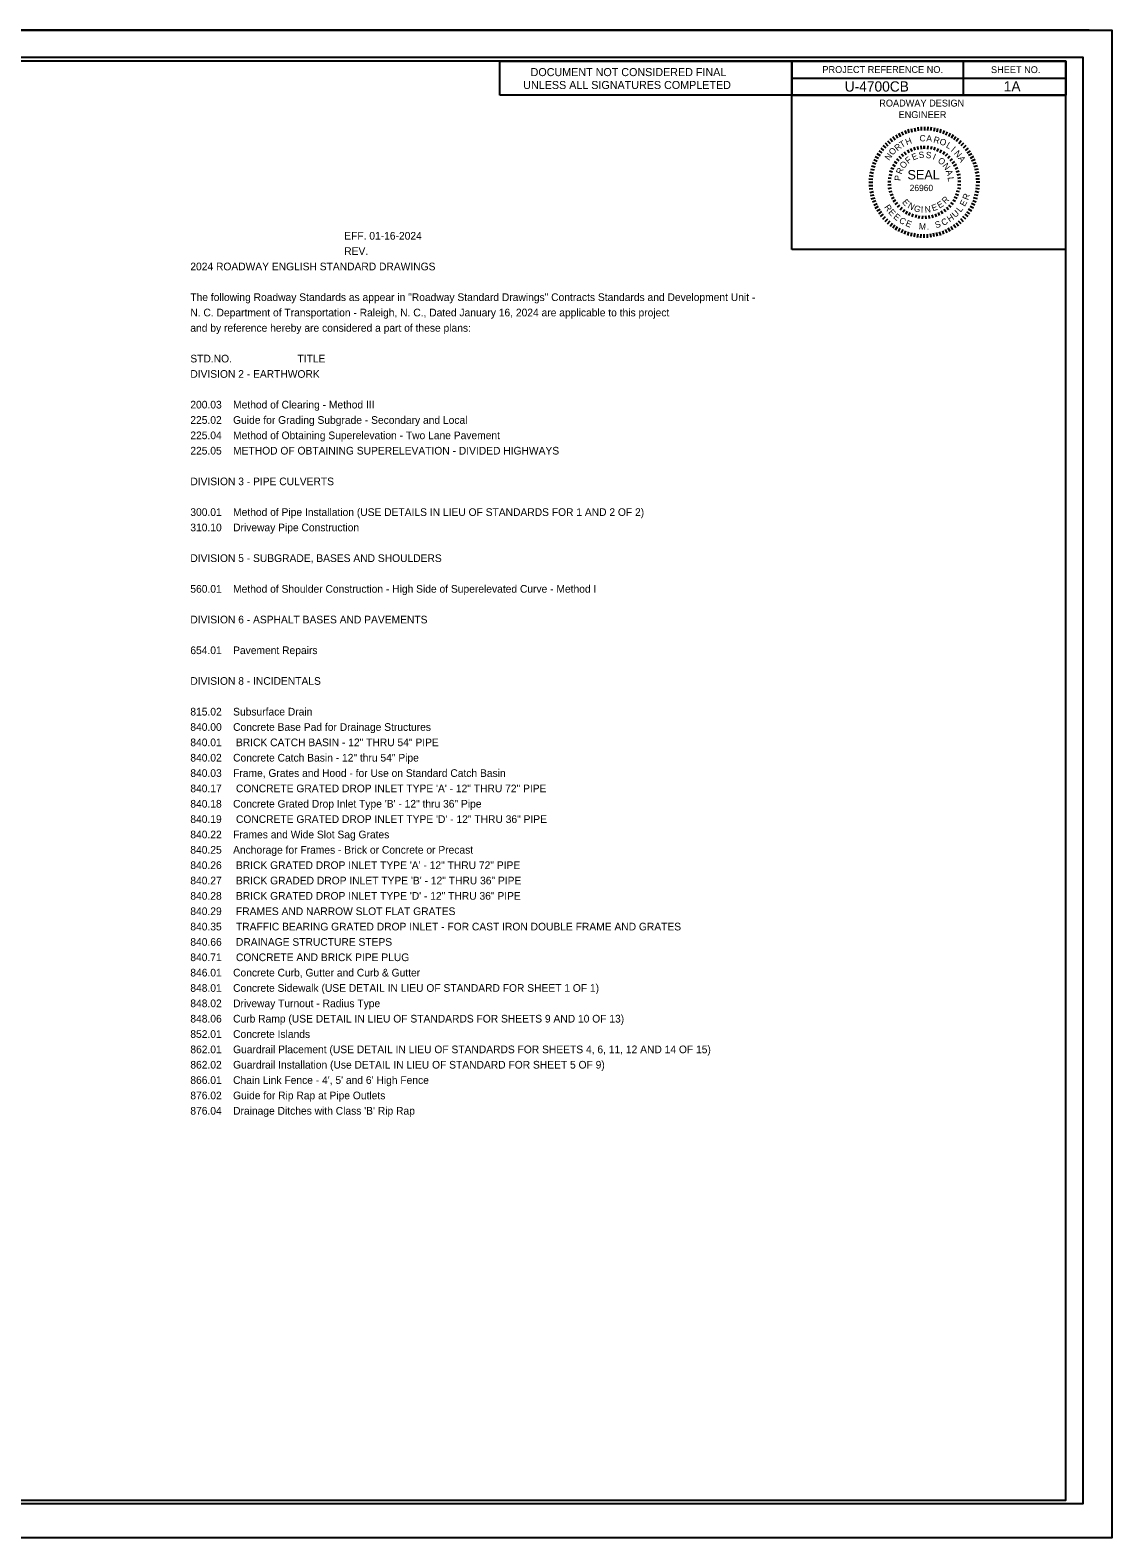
# Model space of a CAD drawing. Extents: x 573687 to 575387, y -53365 to -52265.
# Drawn here: x 574597 to 575387, y -53365 to -52265 of the extents above; entities that cross this region are included whole.
import ezdxf

# ---------------------------------------------------------------- set-up
doc = ezdxf.new("R2010")
doc.units = 0
for name, color, linetype in [('Default', 7, 'Continuous'), ('Sheet Cutting Line CELL', 7, 'Continuous'), ('Sheet Data Field CELL', 7, 'Continuous'), ('Sheet Data Text CELL', 7, 'Continuous'), ('Sheet Plan CELL', 7, 'Continuous'), ('Sheet Plot Border Inside CELL', 7, 'Continuous'), ('Sheet Plot Border Outside CELL', 7, 'Continuous'), ('Sheet Sticker Exception Certification CELL', 7, 'Continuous')]:
    doc.layers.add(name, color=color, linetype=linetype)

msp = doc.modelspace()

# ---------------------------------------------------------------- linework, layer by layer
at = {"layer": 'Default'}
for p, q in [((575237.8, -52337.2), (575238.6, -52339.9)), ((575240.2, -52336.6), (575240.8, -52339.2)), ((575242.6, -52336.1), (575243, -52338.8)), ((575245, -52335.7), (575245.3, -52338.4)), ((575247.4, -52335.5), (575247.6, -52338.2)), ((575249.9, -52335.4), (575249.9, -52338.2)), ((575252.3, -52335.5), (575252.1, -52338.2)), ((575254.7, -52335.7), (575254.4, -52338.4)), ((575257.2, -52336.1), (575256.7, -52338.8)), ((575259.5, -52336.6), (575258.9, -52339.3)), ((575261.9, -52337.2), (575261.1, -52339.9)), ((575221.2, -52347.2), (575223.2, -52349.2)), ((575223, -52345.6), (575224.8, -52347.6)), ((575224.9, -52344), (575226.6, -52346.2)), ((575226.8, -52342.5), (575228.4, -52344.8)), ((575228.9, -52341.2), (575230.3, -52343.6)), ((575231, -52340), (575232.3, -52342.5)), ((575233.2, -52339), (575234.4, -52341.5)), ((575235.5, -52338), (575236.5, -52340.6)), ((575264.2, -52338), (575263.2, -52340.6)), ((575266.5, -52339), (575265.3, -52341.5)), ((575268.7, -52340), (575267.4, -52342.5)), ((575270.8, -52341.3), (575269.4, -52343.6)), ((575272.9, -52342.6), (575271.3, -52344.9)), ((575274.8, -52344), (575273.1, -52346.2)), ((575276.7, -52345.6), (575274.9, -52347.7)), ((575278.5, -52347.3), (575276.5, -52349.2)), ((575212.9, -52359.2), (575215.4, -52360.4)), ((575214, -52357), (575216.4, -52358.3)), ((575215.2, -52354.9), (575217.5, -52356.3)), ((575216.5, -52352.9), (575218.8, -52354.4)), ((575218, -52350.9), (575220.1, -52352.6)), ((575219.5, -52349), (575221.6, -52350.8)), ((575229.4, -52358.7), (575231.2, -52360.1)), ((575231.2, -52356.8), (575232.8, -52358.4)), ((575233.1, -52355.1), (575234.6, -52356.9)), ((575235.2, -52353.6), (575236.5, -52355.5)), ((575237.4, -52352.2), (575238.5, -52354.3)), ((575239.8, -52351.2), (575240.6, -52353.3)), ((575242.2, -52350.3), (575242.9, -52352.5)), ((575244.7, -52349.7), (575245.1, -52352)), ((575247.3, -52349.3), (575247.5, -52351.6)), ((575249.8, -52349.2), (575249.8, -52351.5)), ((575249.8, -52351.5), (575249.8, -52349.2)), ((575252.4, -52349.3), (575252.2, -52351.6)), ((575255, -52349.7), (575254.5, -52352)), ((575257.5, -52350.3), (575256.8, -52352.5)), ((575259.9, -52351.2), (575259, -52353.3)), ((575262.2, -52352.3), (575261.2, -52354.3)), ((575264.5, -52353.6), (575263.2, -52355.5)), ((575266.6, -52355.1), (575265.1, -52356.9)), ((575268.5, -52356.8), (575266.9, -52358.5)), ((575270.2, -52358.7), (575268.5, -52360.2)), ((575280.2, -52349.1), (575278.1, -52350.9)), ((575281.7, -52350.9), (575279.5, -52352.6)), ((575283.2, -52352.9), (575280.9, -52354.5)), ((575284.5, -52355), (575282.1, -52356.4)), ((575285.7, -52357.1), (575283.2, -52358.4)), ((575286.8, -52359.3), (575284.2, -52360.4)), ((575209.6, -52371), (575212.4, -52371.3)), ((575210, -52368.6), (575212.7, -52369.1)), ((575210.5, -52366.2), (575213.2, -52366.8)), ((575211.2, -52363.8), (575213.8, -52364.6)), ((575212, -52361.5), (575214.5, -52362.5)), ((575223.8, -52370.1), (575226, -52370.6)), ((575224.4, -52367.6), (575226.6, -52368.3)), ((575225.4, -52365.2), (575227.5, -52366.1)), ((575226.5, -52362.9), (575228.5, -52364)), ((575227.9, -52360.7), (575229.8, -52362)), ((575271.8, -52360.8), (575269.9, -52362.1)), ((575273.2, -52362.9), (575271.1, -52364.1)), ((575274.3, -52365.3), (575272.2, -52366.2)), ((575275.2, -52367.7), (575273, -52368.4)), ((575275.9, -52370.2), (575273.6, -52370.7)), ((575287.7, -52361.6), (575285.1, -52362.5)), ((575288.5, -52363.9), (575285.9, -52364.7)), ((575289.1, -52366.2), (575286.5, -52366.9)), ((575289.7, -52368.6), (575286.9, -52369.1)), ((575209.3, -52375.9), (575212.1, -52375.9)), ((575209.4, -52373.4), (575212.1, -52373.6)), ((575209.4, -52378.3), (575212.1, -52378.1)), ((575209.6, -52380.7), (575212.3, -52380.4)), ((575223.1, -52375.2), (575225.4, -52375.3)), ((575223.2, -52377.8), (575225.5, -52377.6)), ((575223.3, -52372.7), (575225.6, -52372.9)), ((575223.5, -52380.4), (575225.8, -52380)), ((575273.9, -52379.9), (575276.1, -52380.3)), ((575276.3, -52372.7), (575274, -52373)), ((575276.4, -52377.9), (575274.1, -52377.7)), ((575276.5, -52375.3), (575274.2, -52375.3)), ((575290, -52371.1), (575287.3, -52371.4)), ((575290, -52380.8), (575287.3, -52380.5)), ((575290.2, -52373.5), (575287.5, -52373.6)), ((575290.2, -52378.4), (575287.5, -52378.2)), ((575290.3, -52375.9), (575287.6, -52375.9)), ((575210, -52383.2), (575212.7, -52382.7)), ((575210.5, -52385.5), (575213.2, -52384.9)), ((575211.1, -52387.9), (575213.8, -52387.1)), ((575211.9, -52390.2), (575214.5, -52389.2)), ((575212.9, -52392.5), (575215.4, -52391.4)), ((575224.1, -52382.9), (575226.3, -52382.3)), ((575224.8, -52385.3), (575227, -52384.5)), ((575225.9, -52387.7), (575227.9, -52386.7)), ((575227.1, -52390), (575229.1, -52388.7)), ((575228.6, -52392.1), (575230.4, -52390.7)), ((575230.3, -52394.1), (575231.9, -52392.5)), ((575269.3, -52394.1), (575267.7, -52392.5)), ((575271, -52392.1), (575269.2, -52390.7)), ((575272.5, -52390), (575270.5, -52388.8)), ((575273.7, -52387.7), (575271.7, -52386.7)), ((575274.8, -52385.4), (575272.6, -52384.6)), ((575275.6, -52382.9), (575273.3, -52382.3)), ((575286.7, -52392.5), (575284.2, -52391.4)), ((575287.7, -52390.3), (575285.1, -52389.3)), ((575288.5, -52388), (575285.8, -52387.2)), ((575289.1, -52385.6), (575286.5, -52385)), ((575289.6, -52383.2), (575286.9, -52382.7)), ((575213.9, -52394.7), (575216.4, -52393.4)), ((575215.1, -52396.8), (575217.5, -52395.4)), ((575216.5, -52398.9), (575218.7, -52397.3)), ((575217.9, -52400.8), (575220.1, -52399.1)), ((575219.5, -52402.7), (575221.5, -52400.9)), ((575221.2, -52404.5), (575223.1, -52402.6)), ((575232.1, -52395.9), (575233.6, -52394.1)), ((575234.1, -52397.5), (575235.5, -52395.6)), ((575236.3, -52398.9), (575237.4, -52396.9)), ((575238.5, -52400.1), (575239.5, -52398)), ((575240.9, -52401.1), (575241.7, -52398.9)), ((575243.9, -52399.6), (575243.4, -52401.8)), ((575245.9, -52402.3), (575246.3, -52400)), ((575248.5, -52402.6), (575248.6, -52400.3)), ((575251.1, -52402.6), (575251, -52400.3)), ((575253.6, -52402.3), (575253.3, -52400)), ((575256.2, -52401.8), (575255.6, -52399.6)), ((575258.6, -52401.1), (575257.9, -52398.9)), ((575261, -52400.1), (575260.1, -52398)), ((575263.3, -52398.9), (575262.2, -52396.9)), ((575265.5, -52397.5), (575264.1, -52395.6)), ((575267.5, -52395.9), (575266, -52394.2)), ((575278.4, -52404.6), (575276.5, -52402.6)), ((575280.1, -52402.8), (575278, -52400.9)), ((575281.7, -52400.9), (575279.5, -52399.2)), ((575283.1, -52398.9), (575280.9, -52397.4)), ((575284.5, -52396.9), (575282.1, -52395.4)), ((575285.7, -52394.7), (575283.2, -52393.5)), ((575222.9, -52406.2), (575224.8, -52404.1)), ((575224.8, -52407.8), (575226.5, -52405.6)), ((575226.8, -52409.2), (575228.3, -52406.9)), ((575228.8, -52410.5), (575230.3, -52408.2)), ((575231, -52411.7), (575232.2, -52409.3)), ((575233.2, -52412.8), (575234.3, -52410.3)), ((575235.4, -52413.8), (575236.4, -52411.2)), ((575237.7, -52414.6), (575238.6, -52411.9)), ((575240.1, -52415.2), (575240.7, -52412.5)), ((575242.5, -52415.7), (575243, -52413)), ((575244.9, -52416.1), (575245.2, -52413.4)), ((575247.3, -52416.3), (575247.5, -52413.6)), ((575249.8, -52416.4), (575249.8, -52413.6)), ((575252.2, -52416.3), (575252.1, -52413.6)), ((575254.7, -52416.1), (575254.3, -52413.4)), ((575257.1, -52415.7), (575256.6, -52413)), ((575259.5, -52415.2), (575258.8, -52412.5)), ((575261.8, -52414.6), (575261, -52411.9)), ((575264.1, -52413.8), (575263.2, -52411.2)), ((575266.4, -52412.8), (575265.3, -52410.3)), ((575268.6, -52411.8), (575267.3, -52409.3)), ((575270.7, -52410.6), (575269.3, -52408.2)), ((575272.8, -52409.2), (575271.2, -52407)), ((575274.8, -52407.8), (575273.1, -52405.6)), ((575276.6, -52406.2), (575274.8, -52404.2))]:
    msp.add_line(p, q, dxfattribs=at)
at = {"layer": 'Sheet Cutting Line CELL'}
msp.add_line((575370.2, -52264.9), (573686.7, -52264.9), dxfattribs=at)
at = {"layer": 'Sheet Plan CELL'}
for p, q in [((575278.2, -52287.4), (575278.2, -52312.4)), ((575153.2, -52299.9), (575353.2, -52299.9)), ((575153.2, -52312.4), (575353.2, -52312.4)), ((575153.2, -52312.4), (575353.2, -52312.4)), ((575153.2, -52424.9), (575153.2, -52312.4)), ((575221.8, -52312.4), (575353.2, -52312.4)), ((575353.2, -52424.9), (575153.2, -52424.9))]:
    msp.add_line(p, q, dxfattribs=at)
for points in [[(575353.2, -52287.4), (573853.2, -52287.4), (573853.2, -53337.4), (575353.2, -53337.4)], [(575153.2, -52287.4), (575353.2, -52287.4), (575353.2, -52312.4), (575153.2, -52312.4)]]:
    msp.add_lwpolyline(points, close=True, dxfattribs=at)
at = {"layer": 'Sheet Plot Border Inside CELL'}
msp.add_lwpolyline([(573699.7, -53339.9), (575365.7, -53339.9), (575365.7, -52284.9), (573699.7, -52284.9)], close=True, dxfattribs=at)
at = {"layer": 'Sheet Plot Border Outside CELL'}
msp.add_lwpolyline([(573686.7, -52264.9), (575386.7, -52264.9), (575386.7, -53364.9), (573686.7, -53364.9)], close=True, dxfattribs=at)
at = {"layer": 'Sheet Sticker Exception Certification CELL'}
for p, q in [((574939.9, -52312.4), (574939.9, -52287.4)), ((574939.9, -52287.4), (575153.2, -52287.4)), ((575153.2, -52287.4), (575153.2, -52312.4)), ((575153.2, -52312.4), (574939.9, -52312.4))]:
    msp.add_line(p, q, dxfattribs=at)

# ---------------------------------------------------------------- texts
at = {"layer": 'Default'}
for s, height, rotation, p in [('R', 4.6, 38.6075, (575230.2, -52353.4)), ('T', 4.6, 30.4466, (575233.3, -52350.9)), ('H', 4.6, 21.0146, (575237, -52348.9)), ('C', 4.6, 357.3039, (575246.2, -52345.9)), ('A', 4.6, 357.3039, (575251.2, -52346)), ('R', 4.6, 345.2946, (575256.1, -52346.7)), ('O', 4.6, 342.2378, (575260.5, -52348)), ('L', 4.6, 329.1015, (575265.2, -52350.1)), ('N', 4.6, 53.6237, (575224.2, -52360.4)), ('O', 4.6, 51.6643, (575226.9, -52356.5)), ('F', 4.6, 38.1876, (575238, -52362.6)), ('E', 4.6, 22.8914, (575241.7, -52360)), ('S', 4.6, 7.5951, (575246, -52358.4)), ('S', 4.6, 352.2989, (575250.6, -52358)), ('I', 4.6, 337.0026, (575255.5, -52359)), ('O', 4.6, 321.7064, (575259.2, -52360.8)), ('I', 4.6, 319.5261, (575268.9, -52352.8)), ('N', 4.6, 310.2316, (575271.2, -52354.9)), ('A', 4.6, 300.4641, (575274.2, -52358.3)), ('P', 4.6, 84.0763, (575232.5, -52375)), ('R', 4.6, 68.7801, (575233.2, -52370.4)), ('O', 4.6, 53.4838, (575235, -52366.3)), ('SEAL', 6.9, 359.947, (575237.5, -52373.8)), ('N', 4.6, 306.4101, (575262.8, -52363.9)), ('A', 4.6, 291.1139, (575265.3, -52367.7)), ('26960', 4.6, 359.947, (575239.1, -52382.3)), ('L', 4.6, 275.8176, (575266.8, -52372.2)), ('R', 4.6, 303.882, (575220.3, -52394)), ('E', 4.6, 310.0171, (575233.3, -52390.5)), ('N', 4.6, 330.8721, (575237.2, -52394.3)), ('G', 4.6, 339.6384, (575241.7, -52396.5)), ('E', 4.6, 20.7549, (575256.1, -52397.1)), ('E', 4.6, 30.7408, (575260.8, -52395.1)), ('R', 4.6, 44.5119, (575265.2, -52391.9)), ('E', 4.6, 60.9466, (575279.3, -52393.9)), ('R', 4.6, 69.6194, (575281.7, -52389.2)), ('E', 4.6, 311.9538, (575223.2, -52398)), ('E', 4.6, 320.5966, (575226.8, -52401.7)), ('C', 4.6, 329.2691, (575230.9, -52404.9)), ('E', 4.6, 338.2416, (575235.7, -52407.5)), ('I', 4.6, 357.7332, (575247.2, -52398)), ('N', 4.6, 5.3628, (575250.3, -52398.1)), ('C', 4.6, 25.5662, (575263.5, -52407.7)), ('H', 4.6, 34.3888, (575268.3, -52405.1)), ('U', 4.6, 43.2714, (575272.4, -52402)), ('L', 4.6, 52.154, (575276.3, -52398.1)), ('M', 4.6, 356.0369, (575245.7, -52410.2)), ('.', 4.6, 3.7793, (575251.7, -52410.4)), ('S', 4.6, 16.5636, (575258.3, -52409.4))]:
    msp.add_text(s, height=height, rotation=rotation, dxfattribs=at).set_placement(p)
at = {"layer": 'Sheet Data Field CELL'}
for s, p in [('U-4700CB', (575191.7, -52309.7)), ('1A ', (575307.8, -52309.6))]:
    msp.add_text(s, height=7.5, dxfattribs=at).set_placement(p)
at = {"layer": 'Sheet Data Text CELL'}
for s, p in [('                                                      EFF. 01-16-2024', (574714, -52417.7)), ('                                                      REV. ', (574714, -52428.9)), ('2024 ROADWAY ENGLISH STANDARD DRAWINGS', (574714, -52440.1)), ('The following Roadway Standards as appear in "Roadway Standard Drawings" Contracts Standards and Development Unit -', (574714, -52462.5)), ('N. C. Department of Transportation - Raleigh, N. C., Dated January 16, 2024 are applicable to this project', (574714, -52473.7)), ('and by reference hereby are considered a part of these plans:', (574714, -52484.9)), ('STD.NO.                       TITLE', (574714, -52507.3)), ('DIVISION 2 - EARTHWORK', (574714, -52518.5)), ('200.03    Method of Clearing - Method III', (574714, -52540.9)), ('225.02    Guide for Grading Subgrade - Secondary and Local', (574714, -52552.1)), ('225.04    Method of Obtaining Superelevation - Two Lane Pavement', (574714, -52563.3)), ('225.05    METHOD OF OBTAINING SUPERELEVATION - DIVIDED HIGHWAYS', (574714, -52574.5)), ('DIVISION 3 - PIPE CULVERTS', (574714, -52596.9)), ('300.01    Method of Pipe Installation (USE DETAILS IN LIEU OF STANDARDS FOR 1 AND 2 OF 2)', (574714, -52619.3)), ('310.10    Driveway Pipe Construction', (574714, -52630.5)), ('DIVISION 5 - SUBGRADE, BASES AND SHOULDERS', (574714, -52652.9)), ('560.01    Method of Shoulder Construction - High Side of Superelevated Curve - Method I', (574714, -52675.3)), ('DIVISION 6 - ASPHALT BASES AND PAVEMENTS', (574714, -52697.7)), ('654.01    Pavement Repairs', (574714, -52720.1)), ('DIVISION 8 - INCIDENTALS', (574714, -52742.5)), ('815.02    Subsurface Drain', (574714, -52764.9)), ('840.00    Concrete Base Pad for Drainage Structures', (574714, -52776.1)), ('840.01     BRICK CATCH BASIN - 12" THRU 54" PIPE', (574714, -52787.3)), ('840.02    Concrete Catch Basin - 12" thru 54" Pipe', (574714, -52798.5)), ('840.03    Frame, Grates and Hood - for Use on Standard Catch Basin', (574714, -52809.7)), ('840.17     CONCRETE GRATED DROP INLET TYPE \'A\' - 12" THRU 72" PIPE', (574714, -52820.9)), ('840.18    Concrete Grated Drop Inlet Type \'B\' - 12" thru 36" Pipe', (574714, -52832.1)), ('840.19     CONCRETE GRATED DROP INLET TYPE \'D\' - 12" THRU 36" PIPE', (574714, -52843.3)), ('840.22    Frames and Wide Slot Sag Grates', (574714, -52854.5)), ('840.25    Anchorage for Frames - Brick or Concrete or Precast', (574714, -52865.7)), ('840.26     BRICK GRATED DROP INLET TYPE \'A\' - 12" THRU 72" PIPE', (574714, -52876.9)), ('840.27     BRICK GRADED DROP INLET TYPE \'B\' - 12" THRU 36" PIPE', (574714, -52888.1)), ('840.28     BRICK GRATED DROP INLET TYPE \'D\' - 12" THRU 36" PIPE', (574714, -52899.3)), ('840.29     FRAMES AND NARROW SLOT FLAT GRATES', (574714, -52910.5)), ('840.35     TRAFFIC BEARING GRATED DROP INLET - FOR CAST IRON DOUBLE FRAME AND GRATES', (574714, -52921.7)), ('840.66     DRAINAGE STRUCTURE STEPS', (574714, -52932.9)), ('840.71     CONCRETE AND BRICK PIPE PLUG', (574714, -52944.1)), ('846.01    Concrete Curb, Gutter and Curb & Gutter', (574714, -52955.3)), ('848.01    Concrete Sidewalk (USE DETAIL IN LIEU OF STANDARD FOR SHEET 1 OF 1)', (574714, -52966.5)), ('848.02    Driveway Turnout - Radius Type', (574714, -52977.7)), ('848.06    Curb Ramp (USE DETAIL IN LIEU OF STANDARDS FOR SHEETS 9 AND 10 OF 13)', (574714, -52988.9)), ('852.01    Concrete Islands', (574714, -53000.1)), ('862.01    Guardrail Placement (USE DETAIL IN LIEU OF STANDARDS FOR SHEETS 4, 6, 11, 12 AND 14 OF 15)', (574714, -53011.3)), ('862.02    Guardrail Installation (Use DETAIL IN LIEU OF STANDARD FOR SHEET 5 OF 9)', (574714, -53022.5)), ("866.01    Chain Link Fence - 4', 5' and 6' High Fence", (574714, -53033.7)), ('876.02    Guide for Rip Rap at Pipe Outlets', (574714, -53044.9)), ("876.04    Drainage Ditches with Class 'B' Rip Rap", (574714, -53056.1))]:
    msp.add_text(s, height=5.6, dxfattribs=at).set_placement(p)
at = {"layer": 'Sheet Plan CELL'}
for s, p in [('PROJECT REFERENCE NO.', (575175.4, -52296.1)), ('SHEET NO.', (575298.5, -52296.2)), ('ROADWAY DESIGN', (575216.9, -52320.6)), ('ENGINEER', (575231, -52329))]:
    msp.add_text(s, height=5, dxfattribs=at).set_placement(p)
at = {"layer": 'Sheet Sticker Exception Certification CELL'}
for s, p in [('DOCUMENT NOT CONSIDERED FINAL', (574962.4, -52298.4)), ('UNLESS ALL SIGNATURES COMPLETED', (574957, -52307.8))]:
    msp.add_text(s, height=5.863, dxfattribs=at).set_placement(p)

doc.saveas('drawing.dxf')
